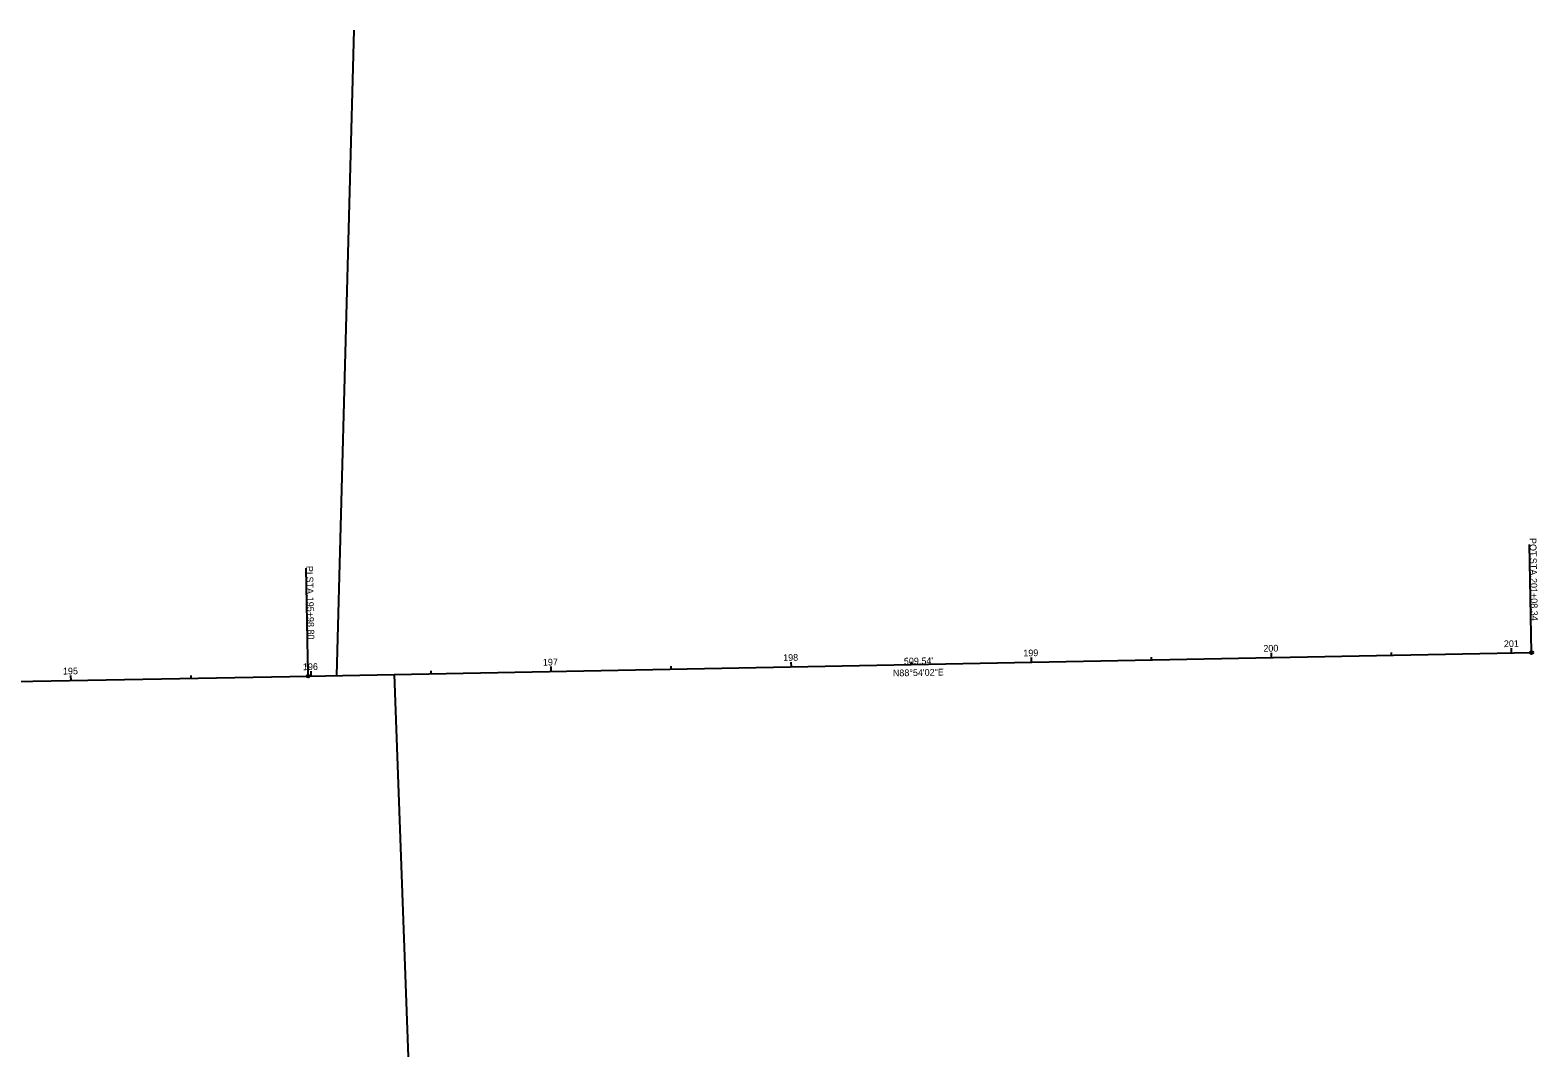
# Model space of a CAD drawing. Extents: x 159250 to 171157, y 552762 to 553239.
# Drawn here: x 170529 to 171157, y 552762 to 553190 of the extents above; entities that cross this region are included whole.
import ezdxf

# ---------------------------------------------------------------- set-up
doc = ezdxf.new("R2010")
doc.units = 0
for name, color, linetype in [('GE_P_Alignment', 7, 'Continuous'), ('GE_P_Alignment_100_Bearings', 7, 'Continuous'), ('GE_P_Alignment_100_Cardinal_Points', 7, 'Continuous'), ('GE_P_Alignment_100_Distances', 7, 'Continuous'), ('GE_P_Alignment_100_Stations', 7, 'Continuous')]:
    doc.layers.add(name, color=color, linetype=linetype)

msp = doc.modelspace()

# ---------------------------------------------------------------- linework, layer by layer
at = {"layer": 'GE_P_Alignment'}
for p, q in [((170656.87, 552920.92), (170664.08, 553189.73)), ((170644.92, 552920.69), (171154.37, 552930.47)), ((169885.75, 552906.95), (170644.92, 552920.69)), ((170680.7, 552921.38), (170686.54, 552762.12))]:
    msp.add_line(p, q, dxfattribs=at)
at = {"layer": 'GE_P_Alignment_100_Cardinal_Points'}
for p, q in [((171154.37, 552930.47), (171153.51, 552975.46)), ((170644.92, 552920.69), (170644.06, 552965.68))]:
    msp.add_line(p, q, dxfattribs=at)
for centre in [(171154.37, 552930.47), (170644.92, 552920.69)]:
    msp.add_circle(centre, 0.6, dxfattribs=at)
at = {"layer": 'GE_P_Alignment_100_Stations'}
for p, q in [((170846.09, 552924.55), (170846.05, 552926.55)), ((170896.08, 552925.51), (170896.06, 552926.71)), ((170946.07, 552926.47), (170946.03, 552928.47)), ((170996.06, 552927.43), (170996.04, 552928.63)), ((171046.05, 552928.39), (171046.01, 552930.39)), ((171096.04, 552929.35), (171096.02, 552930.55)), ((171146.03, 552930.31), (171145.99, 552932.31)), ((170546.14, 552918.9), (170546.1, 552920.9)), ((170596.13, 552919.81), (170596.11, 552921.01)), ((170646.12, 552920.71), (170646.09, 552922.71)), ((170696.12, 552921.67), (170696.09, 552922.87)), ((170746.11, 552922.63), (170746.07, 552924.63)), ((170796.1, 552923.59), (170796.07, 552924.79))]:
    msp.add_line(p, q, dxfattribs=at)

# ---------------------------------------------------------------- texts
at = {"layer": 'GE_P_Alignment_100_Bearings'}
msp.add_text('N88°54\'02"E', height=2.8, rotation=1.09948, dxfattribs=at).set_placement((170888.38, 552920.56))
at = {"layer": 'GE_P_Alignment_100_Cardinal_Points'}
for s, p in [('POT', (171153.5, 552978.18)), ('PI', (170644.08, 552966.58)), (' STA. ', (171153.63, 552970.98)), (' STA. ', (170644.15, 552963.18)), ('201+08.34', (171153.82, 552961.53)), ('195+98.80', (170644.33, 552953.73))]:
    msp.add_text(s, height=2.8, rotation=271.09948, dxfattribs=at).set_placement(p)
at = {"layer": 'GE_P_Alignment_100_Distances'}
msp.add_text("509.54'", height=2.8, rotation=1.09948, dxfattribs=at).set_placement((170892.97, 552925.49))
at = {"layer": 'GE_P_Alignment_100_Stations'}
for s, rotation, p in [('200', 1.09948, (171042.66, 552930.82)), ('201', 1.09948, (171142.83, 552932.74)), ('197', 1.09948, (170742.64, 552925.06)), ('198', 1.09948, (170842.71, 552926.98)), ('199', 1.09948, (170942.7, 552928.9)), ('195', 1.03645, (170542.79, 552921.34)), ('196', 1.09948, (170642.72, 552923.15))]:
    msp.add_text(s, height=2.8, rotation=rotation, dxfattribs=at).set_placement(p)

doc.saveas('drawing.dxf')
